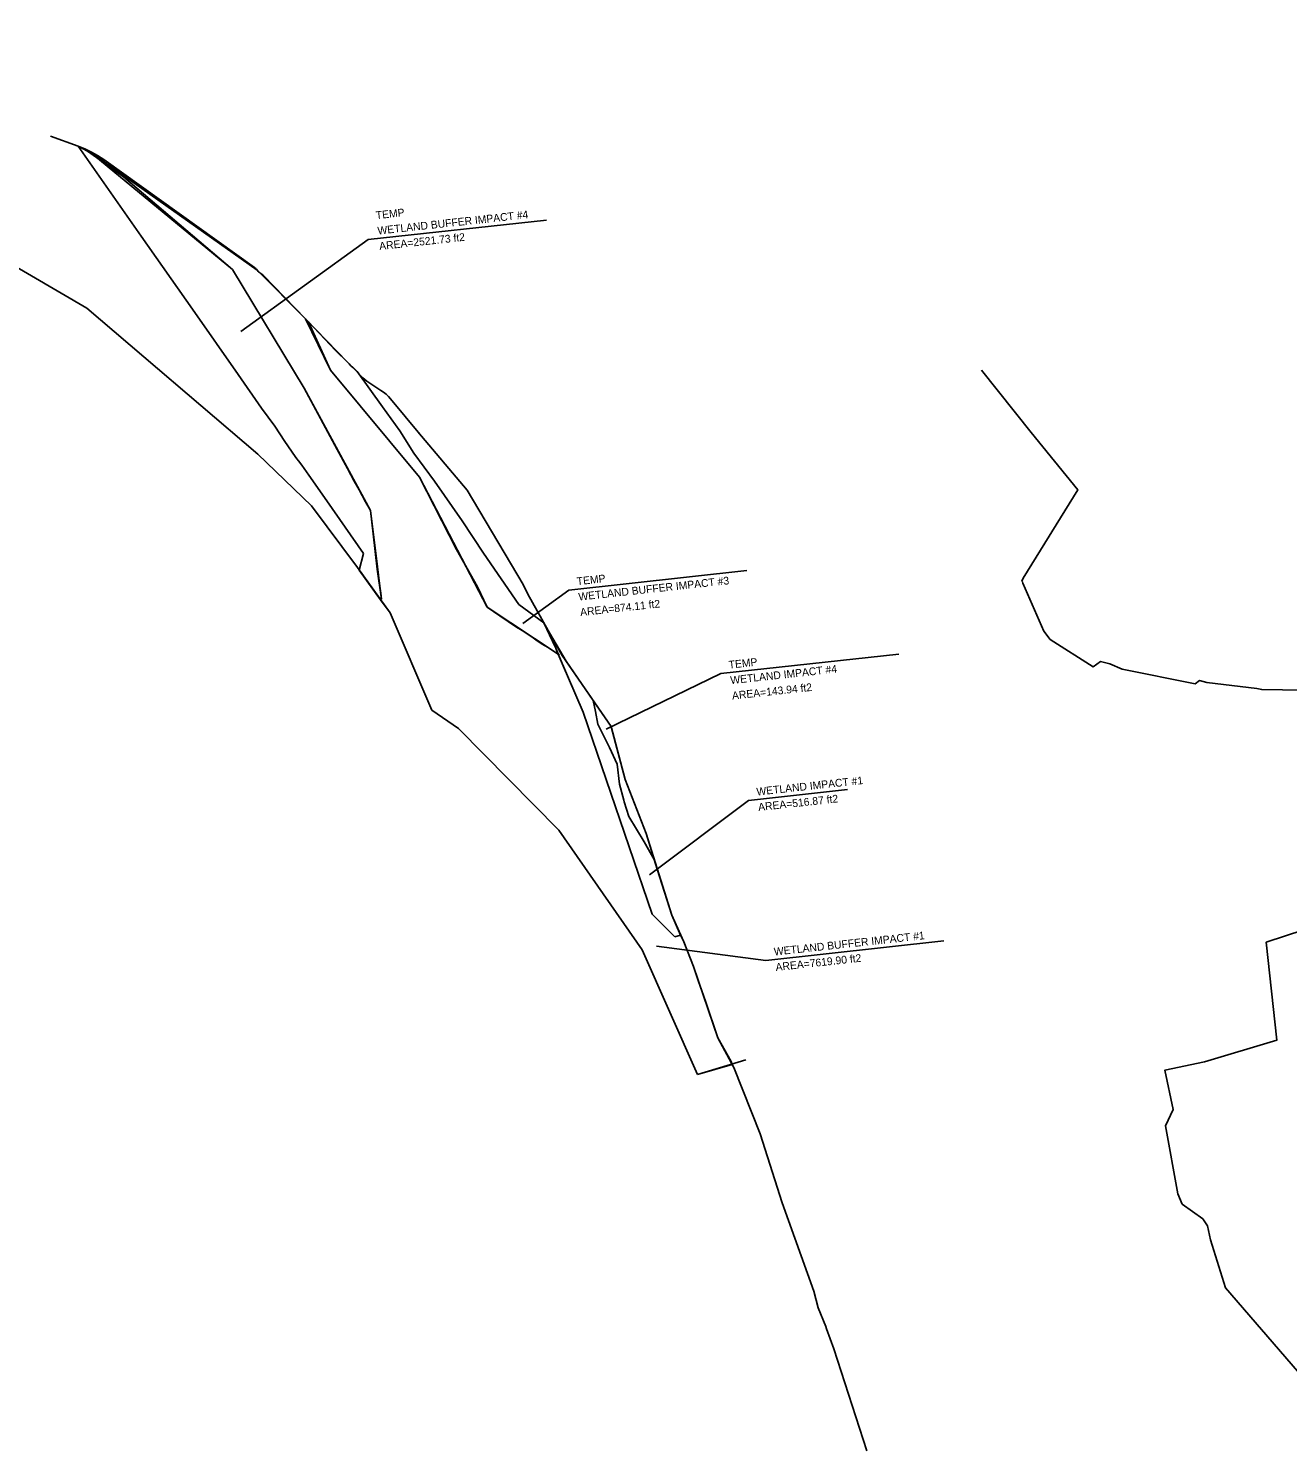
# Model space of a CAD drawing. Extents: x 1509173 to 1510536, y 401169 to 402191.
# Drawn here: x 1509524 to 1509978, y 401680 to 402191 of the extents above; entities that cross this region are included whole.
import ezdxf

# ---------------------------------------------------------------- set-up
doc = ezdxf.new("R2010")
doc.units = 0
for name, color, linetype in [('Default', 7, 'Continuous'), ('EWB_P', 7, 'Continuous'), ('LAWE', 7, 'Continuous'), ('LAWE_P_T', 7, 'Continuous'), ('Level 11', 7, 'Continuous'), ('Level 12', 7, 'Continuous')]:
    doc.layers.add(name, color=color, linetype=linetype)

msp = doc.modelspace()

# ---------------------------------------------------------------- linework, layer by layer
at = {"layer": 'Default'}
for p, q in [((1509606.41, 402103.81), (1509545.34, 402147.07)), ((1509545.34, 402147.07), (1509597.48, 402104.06)), ((1509564.44, 402116.08), (1509582.97, 402089.81)), ((1509597.48, 402104.06), (1509623.32, 402061.25)), ((1509623.85, 402086.26), (1509606.41, 402103.81)), ((1509582.97, 402089.81), (1509599.55, 402066.13)), ((1509632.87, 402067.79), (1509623.85, 402086.26)), ((1509624.91, 402085.19), (1509632.87, 402067.79)), ((1509599.55, 402066.13), (1509607.92, 402054)), ((1509664.94, 402029.15), (1509632.87, 402067.79)), ((1509632.87, 402067.79), (1509664.94, 402029.15)), ((1509623.32, 402061.25), (1509647.28, 402017.06)), ((1509607.92, 402054), (1509612.72, 402047.49)), ((1509612.72, 402047.49), (1509616.4, 402041.94)), ((1509616.4, 402041.94), (1509620.13, 402036.63)), ((1509620.13, 402036.63), (1509620.68, 402035.8)), ((1509624.98, 402029.8), (1509631.46, 402020.54)), ((1509689.42, 401982.17), (1509664.94, 402029.15)), ((1509664.94, 402029.15), (1509678.29, 402002.97)), ((1509647.28, 402017.06), (1509649.77, 401996.76)), ((1509678.29, 402002.97), (1509685.89, 401989.51)), ((1509649.77, 401996.76), (1509650.7, 401989.74)), ((1509643.25, 401995.57), (1509650.92, 401984.85)), ((1509650.7, 401989.74), (1509651.03, 401987.25)), ((1509651.03, 401987.25), (1509651.25, 401985.11)), ((1509685.89, 401989.51), (1509689.42, 401982.17)), ((1509651.25, 401985.11), (1509650.92, 401984.85)), ((1509650.92, 401984.85), (1509651.25, 401985.11)), ((1509715.09, 401965.18), (1509689.42, 401982.17)), ((1509689.42, 401982.17), (1509693.92, 401979.08)), ((1509693.92, 401979.08), (1509699.99, 401974.96)), ((1509699.99, 401974.96), (1509701.5, 401974.13)), ((1509705.98, 401971.08), (1509707.51, 401970.06)), ((1509711.4, 401967.61), (1509715.38, 401964.98)), ((1509715.38, 401964.98), (1509714.69, 401966)), ((1509724.1, 401944.28), (1509715.09, 401965.18)), ((1509669.38, 401944.99), (1509679, 401938.37)), ((1509748.96, 401871.4), (1509724.1, 401944.28)), ((1509679, 401938.37), (1509715.31, 401901.72)), ((1509757.11, 401863.19), (1509748.96, 401871.4)), ((1509759.25, 401863.83), (1509757.11, 401863.19)), ((1509765.56, 401847.42), (1509763.89, 401852.43)), ((1509765.29, 401813.43), (1509777.87, 401817.12))]:
    msp.add_line(p, q, dxfattribs=at)
for points in [[(1509545.05, 402146.87), (1509541.71, 402148.62), (1509564.44, 402116.08)], [(1509645.46, 402020.22), (1509643.16, 402024.54), (1509641.36, 402027.73), (1509638.95, 402032.23), (1509635.3, 402039.16), (1509623.32, 402061.25), (1509597.48, 402104.06), (1509558.09, 402137.57), (1509551.57, 402142.22), (1509545.05, 402146.87)], [(1509688.14, 402001.72), (1509680.33, 402013.38), (1509670.35, 402027.65), (1509662.9, 402037.8), (1509657.83, 402045.88), (1509651.62, 402054.55), (1509642.49, 402067.28), (1509639.01, 402070.61), (1509634.63, 402074.9), (1509624.91, 402085.19)], [(1509620.68, 402035.8), (1509621.34, 402035.04), (1509622.45, 402033.41), (1509624.98, 402029.8)], [(1509631.46, 402020.54), (1509644.71, 402001.61), (1509643.25, 401995.57)], [(1509648.25, 402008.72), (1509647.28, 402017.06), (1509645.46, 402020.22)], [(1509651.25, 401985.11), (1509649.72, 401995.9), (1509648.25, 402008.72)], [(1509713.05, 401969.97), (1509709.89, 401976.48), (1509700.83, 401983.19), (1509688.14, 402001.72)], [(1509650.92, 401984.85), (1509654.33, 401980.09), (1509669.38, 401944.99)], [(1509701.5, 401974.13), (1509702.68, 401973.37), (1509703.88, 401972.57), (1509705.98, 401971.08)], [(1509707.51, 401970.06), (1509709.29, 401968.88), (1509711.4, 401967.61)], [(1509714.69, 401966), (1509714.18, 401967.33), (1509713.05, 401969.97)], [(1509715.31, 401901.72), (1509745.32, 401858.52), (1509765.29, 401813.43)], [(1509763.89, 401852.43), (1509760.37, 401861.31), (1509759.25, 401863.83)], [(1509777.87, 401817.12), (1509777.56, 401818.16), (1509772.7, 401826.65), (1509768.3, 401839.54), (1509765.56, 401847.42)]]:
    msp.add_lwpolyline(points, dxfattribs=at)
at = {"layer": 'EWB_P'}
for points in [[(1509642.59, 401996.49), (1509626.02, 402018.83), (1509606.66, 402037.48), (1509544.92, 402090.17), (1509494.12, 402119.75), (1509466.53, 402112.09), (1509385.67, 402118.98), (1509338.1, 402128.58), (1509278.44, 402190.25), (1509272.19, 402191.17), (1509230.75, 402140.66), (1509172.95, 402136.88)], [(1509669.38, 401944.99), (1509654.33, 401980.09), (1509642.59, 401996.49)], [(1509679, 401938.37), (1509669.38, 401944.99)], [(1509715.31, 401901.72), (1509679, 401938.37)], [(1509765.29, 401813.43), (1509745.32, 401858.52), (1509715.31, 401901.72)], [(1509782.82, 401818.72), (1509765.29, 401813.43)]]:
    msp.add_lwpolyline(points, dxfattribs=at)
at = {"layer": 'LAWE'}
for points in [[(1509665.14, 402044.69), (1509654.52, 402057.36), (1509653.73, 402058.22), (1509652.89, 402059.03), (1509652, 402059.76), (1509651.05, 402060.44), (1509646.63, 402063.32), (1509645.91, 402063.83), (1509645.22, 402064.36), (1509644.56, 402064.94), (1509643.93, 402065.55), (1509641.46, 402068.08), (1509640.85, 402068.72), (1509640.23, 402069.35), (1509639.62, 402069.98), (1509639.01, 402070.61), (1509608.69, 402101.91), (1509608.54, 402102.06), (1509608.39, 402102.19), (1509608.23, 402102.32), (1509608.06, 402102.43), (1509607.36, 402102.88), (1509607.19, 402103), (1509607.04, 402103.13), (1509606.89, 402103.27), (1509606.75, 402103.42), (1509606.08, 402104.2), (1509605.92, 402104.37), (1509605.75, 402104.54), (1509605.57, 402104.69), (1509605.38, 402104.84), (1509550.96, 402143.76), (1509548.77, 402145.22), (1509546.5, 402146.51), (1509544.15, 402147.65), (1509541.71, 402148.62), (1509531.79, 402152.2)], [(1509867.86, 402067.71), (1509885.83, 402045.28), (1509902.63, 402024.52), (1509882.89, 401992.68), (1509882.46, 401991.62), (1509882.63, 401991.29), (1509882.8, 401990.9), (1509890.43, 401973.52), (1509892.64, 401970.54), (1509908.24, 401960.7), (1509910.79, 401962.61), (1509914.24, 401961.76), (1509918.65, 401959.85), (1509945.07, 401954.56), (1509946.65, 401955.7), (1509949.25, 401954.95), (1509967.25, 401952.86), (1509969.07, 401952.46), (1509984.04, 401952.18)], [(1509826.52, 401677.61), (1509814.57, 401714.41), (1509811.96, 401721.64), (1509811.67, 401722.52), (1509808.92, 401729.22), (1509807.37, 401735.22), (1509795.89, 401767.18), (1509787.98, 401792.07), (1509778.47, 401815.96), (1509772.7, 401826.65), (1509763.89, 401852.43), (1509760.37, 401861.31), (1509756.06, 401871.01), (1509746.78, 401900.45), (1509739.21, 401919.95), (1509734.18, 401939.14), (1509716.46, 401964.75), (1509704.07, 401986.85), (1509702.4, 401990.32), (1509682.13, 402024.43), (1509664.43, 402045.53)], [(1509994.99, 401691.34), (1509955.92, 401736.42), (1509950.55, 401753.73), (1509949.47, 401758.83), (1509947.79, 401761.37), (1509940.39, 401766.71), (1509938.72, 401770.41), (1509934.35, 401794.94), (1509937.12, 401800.86), (1509934.08, 401815.08), (1509948.44, 401818.06), (1509974.51, 401825.83), (1509970.69, 401861.22), (1509984.22, 401865.68)]]:
    msp.add_lwpolyline(points, dxfattribs=at)
at = {"layer": 'LAWE_P_T'}
for points in [[(1509600.42, 402081.75), (1509646.5, 402114.89), (1509710.77, 402121.9)], [(1509702.26, 401976.25), (1509718.89, 401988.37), (1509783.16, 401995.38)], [(1509732.38, 401938.09), (1509773.73, 401958.23), (1509838, 401965.24)], [(1509748.05, 401885.52), (1509783.76, 401912.42), (1509819.47, 401916.32)], [(1509750.59, 401859.85), (1509790.06, 401854.66), (1509854.34, 401861.67)]]:
    msp.add_lwpolyline(points, dxfattribs=at)
at = {"layer": 'Level 11'}
for p, q in [((1509716.53, 401961.91), (1509724.1, 401944.28)), ((1509727.68, 401948.52), (1509717.88, 401962.7)), ((1509728.51, 401944.48), (1509727.68, 401948.52)), ((1509724.1, 401944.28), (1509748.96, 401871.4)), ((1509729.4, 401939.94), (1509728.51, 401944.48)), ((1509730.59, 401937.51), (1509729.4, 401939.94)), ((1509733.52, 401931.48), (1509730.59, 401937.51)), ((1509736.33, 401925.51), (1509733.52, 401931.48)), ((1509737.23, 401918.28), (1509736.33, 401925.51)), ((1509740.55, 401906.61), (1509738.92, 401911.95)), ((1509743.35, 401902.05), (1509740.55, 401906.61)), ((1509749.75, 401891.04), (1509748.75, 401892.82)), ((1509750.83, 401887.61), (1509749.75, 401891.04)), ((1509748.96, 401871.4), (1509757.11, 401863.19)), ((1509757.11, 401863.19), (1509759.25, 401863.83))]:
    msp.add_line(p, q, dxfattribs=at)
for points in [[(1509717.88, 401962.7), (1509711.89, 401972.9), (1509716.53, 401961.91)], [(1509738.92, 401911.95), (1509738.8, 401912.46), (1509737.23, 401918.28)], [(1509748.75, 401892.82), (1509746.08, 401897.45), (1509743.35, 401902.05)], [(1509759.25, 401863.83), (1509756.06, 401871.01), (1509750.83, 401887.61)]]:
    msp.add_lwpolyline(points, dxfattribs=at)
at = {"layer": 'Level 12'}
for p, q in [((1509734.18, 401939.14), (1509727.68, 401948.52)), ((1509729.4, 401939.94), (1509730.59, 401937.51)), ((1509730.59, 401937.51), (1509733.52, 401931.48)), ((1509734.22, 401938.99), (1509734.18, 401939.14)), ((1509733.52, 401931.48), (1509736.33, 401925.51)), ((1509738.8, 401912.46), (1509738.92, 401911.95)), ((1509738.92, 401911.95), (1509740.55, 401906.61)), ((1509740.55, 401906.61), (1509743.35, 401902.05)), ((1509749.75, 401891.04), (1509746.78, 401900.45))]:
    msp.add_line(p, q, dxfattribs=at)
for points in [[(1509727.68, 401948.52), (1509728.51, 401944.48), (1509729.4, 401939.94)], [(1509746.78, 401900.45), (1509739.21, 401919.95), (1509734.22, 401938.99)], [(1509736.33, 401925.51), (1509737.23, 401918.28), (1509738.8, 401912.46)], [(1509743.35, 401902.05), (1509746.08, 401897.45), (1509748.75, 401892.82), (1509749.75, 401891.04)]]:
    msp.add_lwpolyline(points, dxfattribs=at)

# ---------------------------------------------------------------- texts
at = {"layer": 'LAWE_P_T'}
for s, p in [('TEMP', (1509649.36, 402122.25)), ('WETLAND BUFFER IMPACT #4', (1509649.97, 402116.69)), ('AREA=2521.73 ft2', (1509650.58, 402111.12)), ('TEMP', (1509721.91, 401990.11)), ('WETLAND BUFFER IMPACT #3', (1509722.51, 401984.54)), ('AREA=874.11 ft2', (1509723.12, 401978.97)), ('TEMP', (1509776.75, 401959.97)), ('WETLAND IMPACT #4', (1509777.36, 401954.4)), ('AREA=143.94 ft2', (1509777.96, 401948.83)), ('WETLAND IMPACT #1', (1509786.79, 401914.16)), ('AREA=516.87 ft2', (1509787.39, 401908.59)), ('WETLAND BUFFER IMPACT #1', (1509793.08, 401856.4)), ('AREA=7619.90 ft2', (1509793.69, 401850.83))]:
    msp.add_text(s, height=2.8, rotation=6.2219, dxfattribs=at).set_placement(p)

doc.saveas('drawing.dxf')
